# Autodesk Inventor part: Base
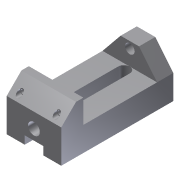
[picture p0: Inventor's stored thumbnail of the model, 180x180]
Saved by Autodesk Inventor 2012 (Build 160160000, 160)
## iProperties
Shininess: 77.0
Length Units: 11269
Angle Units: 11279
Time Units: 11290
Mass Units: 11283
Length Display Precision: 3
Angle Display Precision: 2
Created: 2002-02
Part Number: Base
Document SubType Name: Modeling
Designer: ***
Density: 1 g/cm^3
Material: Default
Density: 0.0
Volumn: 0.0
Area: 0.0
PropertySet Name: Model Information
Control State: 0
Master: False
Checked Out: False
Author: ***
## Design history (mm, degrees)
sketch "Sketch2"
  geometry: L1 (-63.961, -4.254)-(-63.961, -37.254); L2 (-63.961, -37.254)-(88.039, -37.254); L3 (88.039, -37.254)-(88.039, 7.746); L4 (88.039, 7.746)-(68.039, 27.746); L5 (68.039, 27.746)-(58.039, 27.746); L6 (58.039, 27.746)-(58.039, -4.254); L7 (58.039, -4.254)-(-63.961, -4.254)
  constraints: 14 end point, 4 parallel, 1 perpendicular, 1 vertical
  dimensions: "d7" = 10 distance of L4.end L5.end; "d8" = 135 deg angle of L3 L4; "d9" = 33 distance of L1.start L1.end; "d10" = 152 distance of L1.end L2.end; "d11" = 65 distance between parallel lines of L5 L2; "d21" = 30 distance between parallel lines of L3 L6
extrude "Extrusion1" new body sketch "Sketch2" stored distance "d13" = 74; taper "d14" = 0 deg
sketch "Sketch3"
  geometry: L1 (0, 74)-(0, 0) reference; L2 (0, 0)-(-30, 24.5); L3 (-30, 24.5)-(-30, 49.5); L4 (-30, 49.5)-(0, 74); C1 r 6.5 at (-21, 37)
  constraints: 6 end point, 1 centre point, 1 equal length, 1 parallel
  dimensions: "d15" = 25 distance of L2.end L3.end; "d16" = 30 distance between parallel lines of L3 L1; "d17" = 13 diameter of C1; "d18" = 9 distance from line of L3 C1.centre
extrude "Extrusion2" join sketch "Sketch3" distance "d19" = 22; taper "d20" = 0 deg
sketch "Sketch4"
  geometry: L1 (0, 0)-(0, 74) reference; L2 (0, 0)-(45, 0) reference; C1 r 8 at (25, 37)
  constraints: 1 centre point
  dimensions: "d22" = 16 diameter of C1; "d23" = 25 distance from line of L1 C1.centre; "d24" = 37 distance from line of L2 C1.centre
extrude "Extrusion3" cut sketch "Sketch4" distance "d25" = 13; taper "d26" = 0 deg
sketch "Sketch5"
  geometry: L1 (45, 74)-(0, 74) reference; L2 (65, 0)-(65, 74) reference; 1 further point
  dimensions: "d27" = 12 distance from line of point (51, 62) L1; "d28" = 14 distance from line of L2 point (51, 62)
hole "Hole1" sketch "Sketch5" at (51, 62) diameter "d29" = 6; stored, may be unused: countersink angle "d33" = 82 deg, drill point angle "d35" = 0 deg; dims "d30" = 6, "d31" = 8, "d32" = 10, "d34" = 30
mirror "Mirror1"
sketch "Sketch6"
  geometry: L1 (100, 0)-(100, 74) reference; L2 (100, 74)-(0, 74) reference; L3 (14, 45)-(92, 45); L4 (92, 29)-(14, 29); A1 r 8 centre (92, 37) between (92, 29) and (92, 45); A2 r 8 centre (14, 37) between (14, 45) and (14, 29)
  constraints: 4 end point, 4 point on circle, 4 tangent, 2 centre point, 1 horizontal, 1 parallel
  dimensions: "d36" = 8 radius of A2; "d37" = 78 distance of L4.start L4.end; "d38" = 8 distance from line of L1 A1.centre; "d39" = 37 distance from line of L2 A2.centre
extrude "Extrusion4" cut sketch "Sketch6" stored distance "d40" = 13; taper "d41" = 0 deg
sketch "Sketch7"
  geometry: L1 (0, 49.5)-(11, 49.5); L2 (11, 49.5)-(11, 24.5); L3 (11, 24.5)-(0, 24.5); L4 (0, 24.5)-(0, 49.5); L5 (45, 74)-(0, 74) reference; L6 (0, 0)-(0, 74) reference
  constraints: 8 end point, 2 parallel, 1 collinear, 1 horizontal, 1 perpendicular
  dimensions: "d42" = 25 distance of L3.end L1.start; "d43" = 11 distance of L1.start L1.end; "d44" = 24.5 distance between parallel lines of L5 L1
extrude "Extrusion5" cut sketch "Sketch7" stored distance "d45" = 13; taper "d46" = 0 deg
body "Solid1"
